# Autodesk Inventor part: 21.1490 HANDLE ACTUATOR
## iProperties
Created: 2012-03
Part Number: 21.1490 HANDLE ACTUATOR
Document SubType Name: Modeling
Designer: Administrator
Density: 7.85 g/cm^3
Material: Steel
Mass: 50.24 g
Surface Area: 33.28 cm^2
Volume: 6.4 cm^3
Author: Administrator
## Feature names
1. Base1
